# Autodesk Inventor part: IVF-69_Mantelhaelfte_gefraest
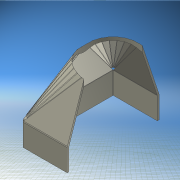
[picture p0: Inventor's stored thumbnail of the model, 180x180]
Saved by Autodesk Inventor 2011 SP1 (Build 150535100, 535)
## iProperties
Created: 2012-03
Part Number: IVF-69_Mantelhaelfte_gefraest
Material: Standard
Document SubType Name: Blech
Designer: Gawin
Mass: 229.183 g
Surface Area: 1204.4 cm^2
Volume: 229.183 cm^3
Density: 1 g/cm^3
Sheet Metal Rule: Standard_mm
Author: Gawin
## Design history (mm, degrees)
derived "IVF-69_Master.ipt"
revolve "Umdrehung1" stored, may be unused: angle "d1" = 90 deg
feature "Volumenkörper1::IVF-69_Master.ipt" dims "d0" = 10
tag "Bezeichnung1"
sketch "Skizze7"
  geometry: L1 (-90.99, 142)-(-65.99, 142) reference; L2 (-65.99, 142)-(-65.99, 70) reference; L3 (-65.99, 70)-(-60.99, 70) reference; L4 (-60.99, 70)-(-60.99, 150) reference; L5 (-60.99, 150)-(-90.99, 150) reference; L6 (-90.99, 150)-(-90.99, 142) reference; L7 (0, -92)-(0, 202) reference; 2 further points
node "Volumenkörper1"
other parameters: "Stärke" = 4 (derived), "KFaktor" = 4.4, "Biegeradius" = 4 (= Stärke), "BreiteBiegungsfreistellung" = 4 (= Stärke), "TiefeBiegungsfreistellung" = 2 (= 0.5 x Stärke), "GrößeEckenfreistellung" = 16 (= 4 x Stärke), "AbstandVerbindung" = 0.01, "MinimalRest" = 8 (= 2 x Stärke), "Übergangsradius" = 4 (= Biegeradius), "JacobiRadiusGröße" = 4 (= Biegeradius), "Abstandsgröße" = 4 (= Stärke)
